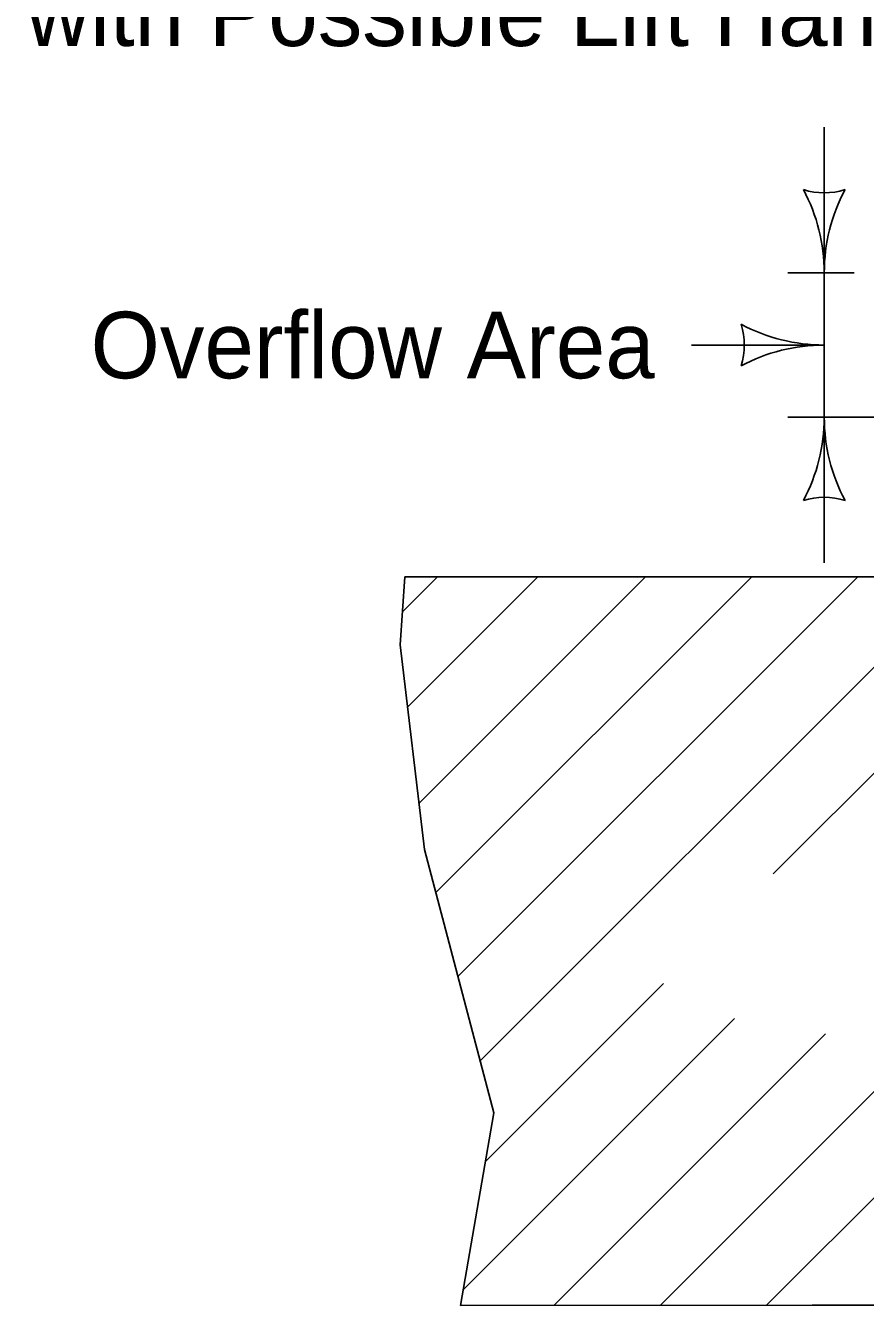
# Model space of a CAD drawing. Extents: x -4827 to -1483, y 910 to 4235.
# Drawn here: x -4551.1 to -4349.3, y 2617.8 to 2925.5 of the extents above; entities that cross this region are included whole.
import ezdxf

# ---------------------------------------------------------------- set-up
doc = ezdxf.new("R2010")
doc.units = 0
for name, color, linetype in [('dsnStdBlock', 7, 'Continuous'), ('dsnStdLabel', 7, 'Continuous'), ('dsnStdNote', 7, 'Continuous'), ('Level 1', 7, 'Continuous')]:
    doc.layers.add(name, color=color, linetype=linetype)

msp = doc.modelspace()

# ---------------------------------------------------------------- linework, layer by layer
at = {"layer": 'dsnStdBlock'}
for p, q in [((-4359.17, 2901.03), (-4359.17, 2796.31)), ((-4367.92, 2866.03), (-4351.96, 2866.03)), ((-4359.17, 2848.67), (-4391.04, 2848.67)), ((-4367.92, 2831.31), (-4345.06, 2831.31))]:
    msp.add_line(p, q, dxfattribs=at)
at = {"layer": 'dsnStdLabel'}
for centre, radius, start, end in [((-4359.17, 2901.67), 16.42, 252.2667, 287.7334), ((-4401.67, 2866.03), 42.5, 0, 28.0725), ((-4316.67, 2866.03), 42.5, 151.9275, 180), ((-4394.8, 2848.67), 16.42, 342.2666, 17.7333), ((-4359.17, 2891.17), 42.5, 241.9275, 270), ((-4359.17, 2806.17), 42.5, 90, 118.0725), ((-4401.67, 2831.31), 42.5, 331.9275, 360), ((-4316.67, 2831.31), 42.5, 180, 208.0725), ((-4359.17, 2795.67), 16.42, 72.2666, 107.7333)]:
    msp.add_arc(centre, radius, start, end, dxfattribs=at)
at = {"layer": 'Level 1'}
for p, q in [((-4460.51, 2784.56), (-4452.09, 2792.98)), ((-4265.1, 2792.87), (-4459.92, 2792.98)), ((-4459.28, 2761.63), (-4427.95, 2792.96)), ((-4456.52, 2738.52), (-4402.1, 2792.95)), ((-4452.48, 2717.05), (-4376.59, 2792.93)), ((-4447.17, 2696.84), (-4351.09, 2792.92)), ((-4441.86, 2676.63), (-4325.59, 2792.9)), ((-4371.43, 2721.54), (-4300.08, 2792.89)), ((-4398.55, 2617.86), (-4265.1, 2751.32)), ((-4373.01, 2617.88), (-4265.1, 2725.8)), ((-4440.58, 2652.39), (-4397.76, 2695.21)), ((-4445.92, 2621.53), (-4380.7, 2686.75)), ((-4424.09, 2617.84), (-4358.85, 2683.08)), ((-4362.11, 2617.89), (-4446.57, 2617.82)), ((-4265.1, 2617.89), (-4362.11, 2617.89))]:
    msp.add_line(p, q, dxfattribs=at)
msp.add_lwpolyline([(-4459.92, 2792.98), (-4461.06, 2776.6), (-4455.19, 2727.37), (-4438.55, 2664.07), (-4446.57, 2617.82)], dxfattribs=at)

# ---------------------------------------------------------------- texts
at = {"layer": 'dsnStdNote'}
for s, p in [('with Possible Lift Handles', (-4551.02, 2920.55)), ('Overflow Area', (-4535.44, 2840.67))]:
    msp.add_text(s, height=16, dxfattribs=at).set_placement(p)

doc.saveas('drawing.dxf')
